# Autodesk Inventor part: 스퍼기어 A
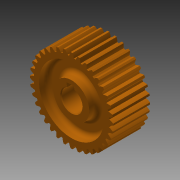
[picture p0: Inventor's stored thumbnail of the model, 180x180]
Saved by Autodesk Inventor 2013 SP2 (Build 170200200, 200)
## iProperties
Created: 2020-04
Part Number: 스퍼기어 A
Material: 강철, 연강
Document SubType Name: Modeling
Designer: mduedu
Categories: <?xml version="1.0" encoding="UTF-16"?> <MemberInstance><Categories><FamilyTemplate><FamilyTemplateParameter ValueType="xs:double" Id="1" ObjectReferenceKey="da
Density: 7.86 g/cm^3
Mass: 321.469 g
Surface Area: 147.737 cm^2
Volume: 40.8993 cm^3
Author: mduedu
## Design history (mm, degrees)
sketch "Sketch1"
  geometry: C1 r 28.2 at (0, 0)
  constraints: 1 centre point
  dimensions: "d0" = 56.4 diameter of C1 (= da_da)
extrude "Extrusion1" new body sketch "Sketch1" distance "d1" = 25 (= da_b); taper "d2" = 0 deg
workplane "Work Plane2"
sketch "Sketch2"
  geometry: C1 r 28.2 at (0, 0) reference; C2 r 27 at (0, 0)
  constraints: 1 centre point, 1 coincident
  dimensions: "d3" = 54 diameter of C2 (= da_dw)
feature "피치 지름" sketch "Sketch2" dims "d4" = 10, "d5" = 0
workplane "Work Plane8"
workplane "Work Plane9"
feature "스퍼 기어" dims "da_b" = 25, "da_d" = 54, "da_aw" = 45, "da_da" = 56.4, "da_df" = 51.129, "da_dw" = 54, angle "da_beta" = 0 deg, "da_lefttooth" = 0, "da_righttooth" = 0
node "작업 평면11"
sketch "스케치3"
  geometry: C1 r 12 at (0, 0); C2 r 22 at (0, 0); 1 further point
  constraints: 2 centre point, 2 coincident
  dimensions: "d49" = 24 diameter of C1; "d50" = 44 diameter of C2
extrude "돌출2" cut sketch "스케치3" distance "d51" = 6; taper "d52" = 0 deg
fillet "모깎기1" dims "d53" = 3
sketch "스케치4" dims "d17" = 0
  geometry: L1 (-3.06, 6.296)-(1.921, 6.731); L2 (1.921, 6.731)-(1.68, 9.483); L3 (1.68, 9.483)-(-3.301, 9.047); L4 (-3.301, 9.047)-(-3.06, 6.296); L5 (-3.728, 42.608)-(3.728, -42.608) reference; A1 r 7 centre (0, 0) between (-3.06, 6.296) and (1.921, 6.731); 1 further point
  constraints: 8 end point, 4 perpendicular, 2 point on circle, 1 centre point, 1 coincident
  dimensions: "d54" = 14 diameter of A1; "d63" = 16.3 dimension on A1 L3; "d64" = 5 distance of L2.end L3.end
extrude "돌출3" cut sketch "스케치4" stored distance "d58" = 6; taper "d59" = 0 deg
chamfer "모따기1" distance "d60" = 0.5; stored, may be unused: second distance "d61" = 2, angle "d62" = 45 deg
body "Solid1"
mirror "대칭1"
body "Srf1"
other parameters: "d16" = 45 (= da_aw), "d34" = 5 deg (computed from da_z), "d39" = 0, "d41" = 0, "d43" = 45 (= da_aw), "d46" = 45 (= da_aw), "d47" = 0, "d48" = 0
